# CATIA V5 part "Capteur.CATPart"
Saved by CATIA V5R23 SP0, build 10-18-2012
Part number: Capteur
Bounding box of the stored display mesh (mm): x -14 to 85, y -25 to 25, z 0 to 30
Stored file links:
  P:\CORRECTION CAO\Capteur.CATPart
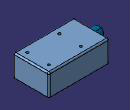
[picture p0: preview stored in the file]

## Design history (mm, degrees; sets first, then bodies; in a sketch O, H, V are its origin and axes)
Body1 (main body)
  Sketch1 on xy-plane, origin (0, 0, 0), H (1, 0, 0), V (0, 1, 0)
    line L1 (85, 25) -> (0, 25)
    line L2 (0, 25) -> (0, -25)
    line L3 (0, -25) -> (85, -25)
    line L4 (85, -25) -> (85, 25)
    point P3 (0, -25)
    reference intersected line E1 through (0, 0) direction (-1, 0) from zx-plane
    distance L3 L1 = 50
    distance L4 L2 = 85
    horizontal: L1 H, L3 H
    vertical: L2 V, L4 V
    coincidence: P3 V
    symmetry: L3 L1 E1
  Pad1: profile Sketch1, direction (0, 0, 1), length 30
  Fillet1: radius 2, on edge [face of Pad1 | face of Pad1] (x8)
  Sketch2 on face of Pad1, origin (71.3283, 11.6885, 30), H (1, 0, 0), V (0, 1, 0)
    point P1 (-41.3283, 3.3115)
    reference intersected line E1 through (0, -11.6885) direction (-1, 0) from zx-plane
    reference intersected line E2 through (-71.3283, 0) direction (0, 1) from yz-plane
    distance E1 P1 = 15
    distance P1 E2 = 30
  Hole1: placed by Sketch2, at (30, 15, 30) direction (0, 0, -1), diameter 3.5, through (limit type 3)
  RectPattern1: of Hole1, direction 1 instances 2, spacing 30, along edge [face of Pad1 | face of Pad1], direction 2 instances 2, spacing 45, along edge [face of Pad1 | face of Pad1]
Body2
  Sketch3 "Esquisse.3" on zx-plane, origin (0, 0, 0), H (-1, 0, 0), V (0, 0, 1)
    line L1 (0, 27) -> (10, 27)
    line L2 (0, 20) -> (0, 27)
    point P2 (10, 27)
    arc A1 centre (5.875, 20) radius 8.125 from (10, 27) to (14, 20) cw
    axis line L3 (0, 20) -> (14, 20)
    reference intersected line E1 (0, 30) -> (0, 0) from face of Pad1
    reference intersected line E2 through (0, 0) direction (-1, 0) from xy-plane
    construction line L4 (14, 32.186) -> (14, 14.8207)
    point P6 (14, 20)
    distance E2 L3 = 20
    distance L3 L1 = 7
    length L1 = 10
    distance L4 P2 = 4
    horizontal: L1 H, L3 H
    vertical: L2 V, L4 V
    coincidence: L2 E1, P6 L4
    tangency: A1 L4
  Shaft1: profile Sketch3, axis Sketch3.L3, angle 360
